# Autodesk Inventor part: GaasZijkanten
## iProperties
Created: 2010-03
Part Number: GaasZijkanten
Document SubType Name: Modeling
Designer: Ferry
Density: 1 g/cm^3
Author: Ferry
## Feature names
1. Extrusion1
